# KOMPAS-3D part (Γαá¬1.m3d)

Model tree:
1. Эскиз:1
2. Операция выдавливания:2
     Расстояние 1 = 3.5; Расстояние 2 = 3.5
3. Скругление:3
     Радиус = 5
4. Скругление:4
     Радиус = 0.1
5. Скругление:5
     Радиус = 0.1
6. Эскиз:3
7. Вырезать элемент выдавливания:2
     Расстояние 1 = 3.5
8. Скругление:6
     Радиус = 0.1

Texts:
  трак1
